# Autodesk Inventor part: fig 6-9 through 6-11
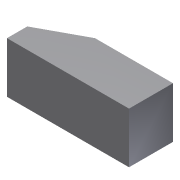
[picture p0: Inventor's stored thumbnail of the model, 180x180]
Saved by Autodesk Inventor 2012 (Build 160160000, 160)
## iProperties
Created: 2009-09
Part Number: fig 6-9 through 6-11
Document SubType Name: Modeling
Designer: Sham
Density: 1 g/cm^3
Material: Default
Author: Sham
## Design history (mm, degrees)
sketch "Sketch1"
  geometry: L1 (-40, 0)-(-40, 12); L2 (-40, 12)-(-14, 26); L3 (-14, 26)-(32.108, 26); L4 (-40, 0)-(32.108, 0); L5 (32.108, 0)-(32.108, 26)
  constraints: 10 end point, 3 perpendicular
extrude "Extrusion1" new body sketch "Sketch1" distance "d0" = 30; taper "d1" = 0 deg
hole "Hole1" diameter "d4" = 10; stored, may be unused: countersink angle "d8" = 90 deg, drill point angle "d10" = 118 deg; dims "d2" = 15, "d3" = 16, "d5" = 6, "d6" = 15, "d7" = 5, "d9" = 12
hole "Hole2" diameter "d13" = 10; stored, may be unused: countersink angle "d17" = 90 deg, drill point angle "d19" = 118 deg; dims "d11" = 12, "d12" = 15, "d14" = 6, "d15" = 15, "d16" = 2, "d18" = 15
hole "Hole3" diameter "d22" = 10; stored, may be unused: countersink angle "d26" = 90 deg, drill point angle "d28" = 118 deg; dims "d20" = 15, "d21" = 15, "d23" = 6, "d24" = 15, "d25" = 2, "d27" = 15
body "Solid1"
